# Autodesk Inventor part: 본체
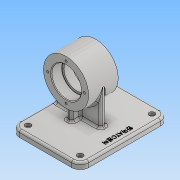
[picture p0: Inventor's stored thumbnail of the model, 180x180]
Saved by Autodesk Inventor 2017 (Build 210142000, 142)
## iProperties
Part Number: 본체
Material: 알루미늄 6061
Document SubType Name: Modeling
Designer: 603-10
Density: 2.7 g/cm^3
Appearance: 알루미늄 - 평지
Mass: 554.63 g
Surface Area: 496.231 cm^2
Volume: 205.419 cm^3
Author: 603-10
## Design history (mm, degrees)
sketch "스케치1"
  geometry: C1 r 32 at (0, 0); 1 further point
  constraints: 1 centre point, 1 coincident
  dimensions: "d0" = 64 diameter of C1
extrude "돌출1" new body sketch "스케치1" stored distance "d1" = 42; taper "d2" = 0 deg
sketch "스케치2"
  geometry: L1 (-62, -50)-(36, -50); L2 (36, -50)-(36, -59); L3 (36, -59)-(-62, -59); L4 (-62, -59)-(-62, -50); 1 further point
  constraints: 8 end point, 2 parallel, 1 horizontal, 1 perpendicular
  dimensions: "d3" = 59 distance from line of L3 point (0, 0); "d4" = 36 distance from line of L2 point (0, 0); "d5" = 9 distance of L3.end L1.start; "d6" = 98 distance of L1.start L1.end
extrude "돌출2" join sketch "스케치2" stored distance "d7" = 126; taper "d8" = 0 deg
sketch "스케치3"
  geometry: L1 (17, 0)-(-17, 0); L2 (-17, 0)-(-17, -50); L3 (-17, -50)-(17, -50); L4 (17, -50)-(17, 0); L5 (-63, -50)-(63, -50) reference; L6 (17, -31.617)-(17, 0); L7 (-17, 0)-(-17, -32.015); 2 further points
  constraints: 12 end point, 3 collinear, 1 coincident, 1 horizontal, 1 midpoint, 1 parallel, 1 perpendicular
  dimensions: "d59" = 34 distance of L1.start L1.end; "d60" = 34 distance of L2.end L3.end
extrude "돌출3" join sketch "스케치3" stored distance "d9" = 8; taper "d10" = 0 deg
sketch "스케치4"
  geometry: L1 (-32, 0)-(32, 0); L2 (32, 0)-(32, -50); L3 (32, -50)-(-32, -50); L4 (-32, -50)-(-32, 0); L5 (-62, -50)-(36, -50) reference; A1 r 32 centre (0, 0) between (-32, 0) and (32, 0) reference; 3 further points
  constraints: 8 end point, 2 parallel, 2 point on circle, 1 collinear, 1 horizontal, 1 perpendicular
  dimensions: "d42" = 64 distance of L1.start L1.end
extrude "돌출4" join sketch "스케치4" stored distance "d12" = 8; taper "d13" = 0 deg
sketch "스케치5"
  geometry: C1 r 21 at (0, 0); 1 further point
  constraints: 1 centre point, 1 coincident
  dimensions: "d14" = 42 diameter of C1
extrude "돌출5" cut sketch "스케치5" distance "d15" = 15; taper "d16" = 0 deg
sketch "스케치6"
  geometry: C1 r 18 at (0, 0); 1 further point
  constraints: 1 centre point, 1 coincident
  dimensions: "d17" = 36 diameter of C1
extrude "돌출6" cut sketch "스케치6" stored distance "d18" = 15; taper "d19" = 0 deg
sketch "스케치7" dims "d20" = 52
  geometry: C1 r 18 at (0, 0) reference; 3 further points
  constraints: 2 vertical alignment, 1 coincident, 3 other
hole "구멍1" sketch "스케치7" at (0, 26) diameter "d21" = 3.242; stored, may be unused: countersink angle "d25" = 90 deg, drill point angle "d27" = 118 deg; dims "d22" = 8, "d23" = 4, "d24" = 2, "d26" = 10
sketch "스케치8" dims "d31" = 52
  geometry: 3 further points
  constraints: 2 vertical alignment, 1 coincident, 2 other
hole "구멍2" sketch "스케치8" at (0, 26) diameter "d32" = 3.242; stored, may be unused: countersink angle "d36" = 90 deg, drill point angle "d38" = 118 deg; dims "d33" = 8, "d34" = 4, "d35" = 2, "d37" = 10
sketch "스케치9"
  geometry: L1 (105.977, -63)-(0.739, -63); L2 (49, -0.384)-(49, -137.369); L3 (0, 0)-(0, -126) reference; L4 (98, -126)-(98, 0) reference; 3 further points
  constraints: 4 end point, 1 horizontal, 1 midpoint, 1 point on line, 1 vertical
  dimensions: "d43" = 102 diameter of point (12, -12) L1; "d44" = 49 distance between parallel lines of L3 L2; "d45" = 74 diameter of point (12, -12) L2
hole "구멍3" sketch "스케치9" at (12, -12) diameter "d46" = 4.5; stored, may be unused: countersink angle "d50" = 90 deg, drill point angle "d52" = 118 deg; dims "d47" = 8, "d48" = 8, "d49" = 4.4, "d51" = 10
fillet "모깎기1" dims "d61" = 3
chamfer "모따기1" distance "d62" = 1; stored, may be unused: second distance "d63" = 2, angle "d64" = 45 deg
fillet "모깎기2" dims "d65" = 12
fillet "모깎기3" dims "d66" = 3
sketch "스케치10"
  geometry: L1 (5, -70)-(79, -70) reference; L2 (91, -58)-(91, 44) reference; 2 further points
  constraints: 1 other
  dimensions: "d67" = 63 distance from line of L1 point (81, -7); "d68" = 10 distance from line of L2 point (81, -7)
feature "엠보싱1" sketch "스케치10" dims "d69" = 0.5, "d70" = 0
fillet "모깎기4" dims "d71" = 0.3
node "솔리드1"
mirror "미러1"
pattern_circular "원형 패턴1" dims angle "d29" = 360 deg
pattern_circular "원형 패턴2" dims angle "d40" = 360 deg
pattern_linear "직사각형 패턴1" dims "d55" = 102, "d58" = 74
